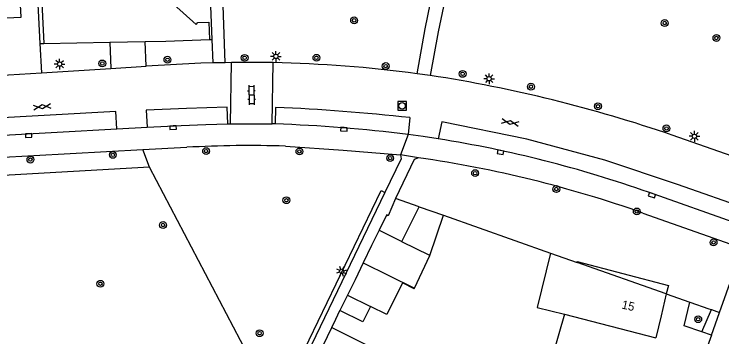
# Model space of a CAD drawing. Extents: x 132999 to 136000, y 398499 to 400501.
# Drawn here: x 133486.8 to 133569.4, y 399164.4 to 399202.1 of the extents above; entities that cross this region are included whole.
import ezdxf

# ---------------------------------------------------------------- set-up
doc = ezdxf.new("R2010")
doc.units = 0
for name, color, linetype in [('gg-afsc-erfafscheiding', 7, 'Continuous'), ('gg-afsc-hekwerk', 7, 'Continuous'), ('gg-afsc-muur', 7, 'Continuous'), ('gg-anno-huisnummerreeks BGT', 7, 'Continuous'), ('gg-bbg-bijgebouw', 7, 'Continuous'), ('gg-bbg-gedigitaliseerde bebouwing', 7, 'Continuous'), ('gg-bbg-gedigitaliseerde bijgebouw', 7, 'Continuous'), ('gg-bbg-hoofdgebouw', 7, 'Continuous'), ('gg-bbg-luifel en loopbrug', 7, 'Continuous'), ('gg-bbg-onder overbouw', 7, 'Continuous'), ('gg-bbg-pand overbouw', 7, 'Continuous'), ('gg-bbg-tussenscheiding', 7, 'Continuous'), ('gg-knt-verharding', 7, 'Continuous'), ('gg-knt-verharding nz', 7, 'Continuous'), ('gt-grn-groengrens', 7, 'Continuous'), ('gt-grn-vlakafsluiter', 7, 'Continuous'), ('gt-grn-weggrens', 7, 'Continuous'), ('gt-symb-boom', 7, 'Continuous'), ('gt-symb-gesloten verharding', 7, 'Continuous'), ('gt-symb-klinker verharding', 7, 'Continuous'), ('gt-symb-kolk', 7, 'Continuous'), ('gt-symb-lichtmast', 7, 'Continuous'), ('gt-symb-rioolschacht', 7, 'Continuous')]:
    doc.layers.add(name, color=color, linetype=linetype)

# ---------------------------------------------------------------- blocks, each defined once
blk = doc.blocks.new('gt0-BOOM')
at = {"layer": 'gt-symb-boom'}
for radius in [0.4, 0.2]:
    blk.add_circle((0, 0), radius, dxfattribs=at)
blk = doc.blocks.new('gt0-LMAST')
at = {"layer": 'gt-symb-lichtmast'}
for p, q in [((-0.182, 0.173), (-0.447, 0.438)), ((-0.005, 0.246), (-0.005, 0.621)), ((0.172, 0.173), (0.437, 0.438)), ((-0.255, -0.004), (-0.63, -0.004)), ((-0.182, -0.181), (-0.447, -0.446)), ((-0.005, -0.254), (-0.005, -0.629)), ((0.437, -0.446), (0.172, -0.181)), ((0.245, -0.004), (0.62, -0.004))]:
    blk.add_line(p, q, dxfattribs=at)
blk.add_circle((-0.005, -0.004), 0.25, dxfattribs=at)
blk = doc.blocks.new('gt0-GESVH1')
at = {"layer": 'gt-symb-gesloten verharding'}
for p, q in [((-0.992, -0.261), (0.008, 0.239)), ((0.008, -0.261), (-0.992, 0.239)), ((0.008, 0.239), (1.008, -0.261)), ((1.008, 0.239), (0.008, -0.261))]:
    blk.add_line(p, q, dxfattribs=at)
blk = doc.blocks.new('gt0-RS')
at = {"layer": 'gt-symb-rioolschacht'}
blk.add_lwpolyline([(-0.5, -0.5), (0.5, -0.5), (0.5, 0.5), (-0.5, 0.5)], close=True, dxfattribs=at)
blk.add_circle((0, 0), 0.375, dxfattribs=at)
blk = doc.blocks.new('gt0-KL1')
at = {"layer": 'gt-symb-klinker verharding'}
for p, q in [((-1.15, 0.3), (1.15, 0.3)), ((-1, -0.3), (-1, 0.3)), ((-0.5, 0.3), (-0.5, 0.45)), ((0, -0.3), (0, 0.3)), ((0.5, 0.3), (0.5, 0.45)), ((1, -0.3), (1, 0.3)), ((-1.15, -0.3), (1.15, -0.3)), ((-0.5, -0.45), (-0.5, -0.3)), ((0.5, -0.45), (0.5, -0.3))]:
    blk.add_line(p, q, dxfattribs=at)
blk = doc.blocks.new('gt0-KOLK')
at = {"layer": 'gt-symb-kolk'}
blk.add_lwpolyline([(0, 0), (0.375, 0), (0.375, 0.4), (-0.375, 0.4), (-0.375, 0), (0, 0)], dxfattribs=at)

msp = doc.modelspace()

# ---------------------------------------------------------------- linework, layer by layer
at = {"layer": 'gg-afsc-erfafscheiding'}
msp.add_line((133524.35, 399166.479), (133524.831, 399167.485), dxfattribs=at)
at = {"layer": 'gg-afsc-hekwerk'}
for p, q in [((133502.555, 399184.214), (133481.552, 399183.03)), ((133515.357, 399159.931), (133502.555, 399184.214))]:
    msp.add_line(p, q, dxfattribs=at)
at = {"layer": 'gg-afsc-muur'}
for p, q in [((133536.917, 399178.597), (133549.437, 399174.167)), ((133562.955, 399169.416), (133565.715, 399168.455)), ((133565.715, 399168.455), (133567.946, 399167.679)), ((133523.869, 399165.472), (133524.35, 399166.479))]:
    msp.add_line(p, q, dxfattribs=at)
at = {"layer": 'gg-bbg-bijgebouw'}
for p, q in [((133534.097, 399179.595), (133531.306, 399180.575)), ((133532.07, 399175.523), (133534.097, 399179.595)), ((133530.262, 399178.601), (133529.39, 399176.846)), ((133529.39, 399176.846), (133528.498, 399175.05)), ((133528.498, 399175.05), (133527.552, 399173.06)), ((133533.519, 399170.093), (133535.328, 399173.884)), ((133527.552, 399173.06), (133526.595, 399171.046)), ((133526.595, 399171.046), (133525.719, 399169.277)), ((133525.719, 399169.277), (133524.831, 399167.485)), ((133533.487, 399170.025), (133533.519, 399170.093)), ((133522.005, 399161.647), (133523.869, 399165.472))]:
    msp.add_line(p, q, dxfattribs=at)
for points in [[(133531.306, 399180.575), (133530.459, 399178.548), (133530.28, 399178.637), (133530.262, 399178.601)], [(133535.328, 399173.884), (133532.061, 399175.505), (133532.07, 399175.523)]]:
    msp.add_lwpolyline(points, dxfattribs=at)
at = {"layer": 'gg-bbg-gedigitaliseerde bebouwing'}
msp.add_line((133551.056, 399167.045), (133549.742, 399162.439), dxfattribs=at)
msp.add_lwpolyline([(133549.437, 399174.167), (133547.87, 399167.833), (133551.056, 399167.045)], dxfattribs=at)
at = {"layer": 'gg-bbg-gedigitaliseerde bijgebouw'}
for points in [[(133533.487, 399170.025), (133532.146, 399170.688), (133530.318, 399166.991), (133528.394, 399167.943)], [(133528.394, 399167.943), (133527.507, 399166.15), (133524.831, 399167.485)], [(133523.869, 399165.472), (133528.861, 399163.011), (133526.857, 399159.095)]]:
    msp.add_lwpolyline(points, dxfattribs=at)
at = {"layer": 'gg-bbg-hoofdgebouw'}
for p, q in [((133509.88, 399199.13), (133509.3, 399214.15)), ((133509.58, 399199.12), (133509.88, 399199.13)), ((133549.437, 399174.167), (133552.546, 399173.067))]:
    msp.add_line(p, q, dxfattribs=at)
for points in [[(133504.25, 399204.32), (133508.01, 399200.88), (133508.23, 399201.1), (133509.5, 399201.15), (133509.58, 399199.12)], [(133562.955, 399169.416), (133562.377, 399166.842), (133561.744, 399164.282)]]:
    msp.add_lwpolyline(points, dxfattribs=at)
at = {"layer": 'gg-bbg-luifel en loopbrug'}
for p in [(133534.097, 399179.595), (133535.328, 399173.884)]:
    msp.add_line(p, (133536.917, 399178.597), dxfattribs=at)
at = {"layer": 'gg-bbg-onder overbouw'}
msp.add_line((133562.955, 399169.416), (133552.546, 399173.067), dxfattribs=at)
at = {"layer": 'gg-bbg-pand overbouw'}
msp.add_lwpolyline([(133552.546, 399173.067), (133552.539, 399173.11), (133552.528, 399173.188), (133563.2, 399170.389), (133562.955, 399169.416)], dxfattribs=at)
at = {"layer": 'gg-bbg-tussenscheiding'}
for p, q in [((133529.39, 399176.846), (133532.07, 399175.523)), ((133527.552, 399173.06), (133533.519, 399170.093)), ((133525.719, 399169.277), (133528.394, 399167.943)), ((133551.056, 399167.045), (133561.744, 399164.282))]:
    msp.add_line(p, q, dxfattribs=at)
at = {"layer": 'gg-knt-verharding'}
for p, q in [((133488.995, 399212.935), (133489.778, 399198.676)), ((133489.778, 399198.676), (133489.966, 399195.258)), ((133490.239, 399198.684), (133497.932, 399198.813)), ((133497.932, 399198.813), (133498.051, 399195.753)), ((133502.083, 399198.882), (133504.483, 399198.922)), ((133502.194, 399196.007), (133502.083, 399198.882)), ((133489.966, 399195.258), (133498.051, 399195.753)), ((133498.051, 399195.753), (133502.194, 399196.007)), ((133511.414, 399196.425), (133510.015, 399196.391)), ((133512.171, 399196.444), (133511.414, 399196.425)), ((133512.036, 399189.288), (133512.171, 399196.444)), ((133517.025, 399196.428), (133512.171, 399196.444)), ((133516.89, 399189.271), (133517.025, 399196.428)), ((133484.29, 399194.91), (133489.966, 399195.258)), ((133535.385, 399194.924), (133533.84, 399195.139)), ((133511.708, 399189.28), (133512.036, 399189.288)), ((133512.036, 399189.288), (133516.89, 399189.271)), ((133517.268, 399189.263), (133516.89, 399189.271)), ((133473.007, 399187.275), (133498.767, 399188.681)), ((133498.767, 399188.681), (133502.312, 399188.875)), ((133588.512, 399179.177), (133563.656, 399187.959)), ((133481.411, 399185.167), (133501.803, 399186.266)), ((133501.803, 399186.266), (133506.935, 399186.542)), ((133533.484, 399185.104), (133531.306, 399180.575)), ((133534.017, 399185.323), (133533.484, 399185.104)), ((133530.082, 399181.265), (133518.38, 399157.026)), ((133572.067, 399177.35), (133560.898, 399181.283)), ((133560.208, 399178.858), (133570.515, 399175.209)), ((133569.174, 399167.252), (133571.826, 399174.745)), ((133568.231, 399164.588), (133569.174, 399167.252)), ((133568.231, 399164.588), (133567.1, 399164.978))]:
    msp.add_line(p, q, dxfattribs=at)
for points in [[(133485.016, 399201.639), (133487.57, 399201.76), (133485.63, 399236.89), (133481.346, 399236.748)], [(133499.912, 399208.347), (133489.758, 399208.177), (133490.239, 399198.684)], [(133533.84, 399195.139), (133534.795, 399200.372), (133535.734, 399204.993), (133536.47, 399208.111)], [(133537.536, 399205.984), (133536.32, 399200.042), (133535.385, 399194.924)], [(133510.015, 399196.391), (133508.573, 399196.355), (133502.194, 399196.007)], [(133502.312, 399188.875), (133506.269, 399189.091), (133509.151, 399189.219), (133511.708, 399189.28)], [(133536.311, 399187.525), (133534.549, 399187.796), (133532.787, 399188.044)], [(133518.457, 399186.679), (133525.183, 399186.212), (133531.902, 399185.655)], [(133531.902, 399185.655), (133531.984, 399185.205), (133530.082, 399181.265)], [(133567.1, 399164.978), (133565.062, 399165.68), (133565.715, 399168.455)]]:
    msp.add_lwpolyline(points, dxfattribs=at)
for centre, radius, start, end in [((133514.072, 399047.582), 148.875, 82.36949, 88.86333), ((133510.548, 399033.253), 163.568, 71.05362, 81.26621), ((133511.698, 399018.955), 170.399, 82.89067, 88.12673), ((133514.001, 399048.1), 141.199, 70.60137, 80.90871), ((133514.333, 399048.951), 137.79, 88.28483, 93.07764), ((133514.357, 399049.39), 137.348, 70.4983, 81.77021)]:
    msp.add_arc(centre, radius, start, end, dxfattribs=at)
at = {"layer": 'gg-knt-verharding nz'}
for p, q in [((133517.307, 399191.202), (133517.268, 399189.263)), ((133532.992, 399190.014), (133532.787, 399188.044)), ((133568.231, 399164.588), (133567.783, 399163.294))]:
    msp.add_line(p, q, dxfattribs=at)
for points in [[(133511.708, 399189.28), (133511.662, 399191.216), (133506.91, 399191.078), (133502.202, 399190.881), (133502.312, 399188.875)], [(133498.767, 399188.681), (133498.656, 399190.706), (133460.223, 399188.59), (133460.333, 399186.582)], [(133572.067, 399177.35), (133572.729, 399179.231), (133564.259, 399182.21), (133555.773, 399185.031), (133546.674, 399187.476), (133536.716, 399189.508), (133536.311, 399187.525)]]:
    msp.add_lwpolyline(points, dxfattribs=at)
msp.add_arc((133506.36, 398942.532), 248.911, 83.85791, 87.47933, dxfattribs=at)
at = {"layer": 'gt-grn-groengrens'}
for p, q in [((133510.015, 399196.391), (133509.88, 399199.13)), ((133489.778, 399198.676), (133490.239, 399198.684)), ((133502.555, 399184.214), (133501.803, 399186.266)), ((133567.946, 399167.679), (133568.25, 399167.573)), ((133567.1, 399164.978), (133568.25, 399167.573)), ((133568.25, 399167.573), (133569.174, 399167.252))]:
    msp.add_line(p, q, dxfattribs=at)
for points in [[(133511.414, 399196.425), (133510.619, 399218.704), (133509.145, 399218.677)], [(133518.072, 399157.5), (133529.647, 399181.475), (133530.082, 399181.265)]]:
    msp.add_lwpolyline(points, dxfattribs=at)
at = {"layer": 'gt-grn-vlakafsluiter'}
msp.add_line((133504.483, 399198.922), (133509.58, 399199.12), dxfattribs=at)
at = {"layer": 'gt-grn-weggrens'}
for p, q in [((133497.932, 399198.813), (133502.083, 399198.882)), ((133532.787, 399188.044), (133531.902, 399185.655)), ((133534.017, 399185.323), (133531.902, 399185.655))]:
    msp.add_line(p, q, dxfattribs=at)

# ---------------------------------------------------------------- block references
at = {"layer": 'gt-symb-boom'}
for p in [(133526.486, 399201.371), (133562.774, 399201.057), (133568.818, 399199.312), (133513.692, 399196.991), (133522.079, 399196.994), (133497.057, 399196.333), (133504.674, 399196.77), (133530.169, 399196.027), (133539.162, 399195.119), (133547.142, 399193.623), (133554.977, 399191.338), (133562.981, 399188.75), (133498.29, 399185.653), (133509.188, 399186.096), (133520.093, 399186.056), (133488.66, 399185.101), (133530.693, 399185.276), (133540.621, 399183.523), (133550.11, 399181.665), (133559.511, 399179.046), (133568.48, 399175.429), (133496.834, 399170.597), (133566.687, 399166.455), (133515.437, 399164.823)]:
    msp.add_blockref('gt0-BOOM', p, dxfattribs=at)
for p, rotation in [((133518.571, 399180.356), 3.0940580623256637), ((133504.156, 399177.461), 3.1543921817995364)]:
    msp.add_blockref('gt0-BOOM', p, dxfattribs=dict(at, rotation=rotation))
at = {"layer": 'gt-symb-gesloten verharding'}
for p, rotation in [((133490.033, 399191.283), 5.853091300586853), ((133544.713, 399189.449), -10.489389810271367)]:
    msp.add_blockref('gt0-GESVH1', p, dxfattribs=dict(at, rotation=rotation))
at = {"layer": 'gt-symb-klinker verharding', "rotation": -88.51064527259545}
msp.add_blockref('gt0-KL1', (133514.492, 399192.66), dxfattribs=at)
at = {"layer": 'gt-symb-kolk'}
for p, rotation in [((133505.325, 399189.043), -177.42085249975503), ((133525.313, 399188.843), 175.3552783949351), ((133488.448, 399188.116), -177.0775273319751), ((133543.627, 399186.149), 168.22937399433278), ((133561.348, 399181.124), 160.18818811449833)]:
    msp.add_blockref('gt0-KOLK', p, dxfattribs=dict(at, rotation=rotation))
at = {"layer": 'gt-symb-lichtmast'}
for p in [(133517.349, 399197.16), (133492.079, 399196.26), (133542.263, 399194.551), (133566.247, 399187.827)]:
    msp.add_blockref('gt0-LMAST', p, dxfattribs=at)
at = {"layer": 'gt-symb-lichtmast', "rotation": -25.92418551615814}
msp.add_blockref('gt0-LMAST', (133525.036, 399172.039), dxfattribs=at)
at = {"layer": 'gt-symb-rioolschacht'}
msp.add_blockref('gt0-RS', (133532.087, 399191.388), dxfattribs=at)

# ---------------------------------------------------------------- texts
at = {"layer": 'gg-anno-huisnummerreeks BGT'}
msp.add_text('15', height=1, rotation=347.4, dxfattribs=at).set_placement((133557.679, 399167.717))

doc.saveas('drawing.dxf')
